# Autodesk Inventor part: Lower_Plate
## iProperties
Shininess: 15.0
Length Units: 11272
Angle Units: 11279
Time Units: 11290
Mass Units: 11283
Length Display Precision: 2
Angle Display Precision: 1
Created: 1999-05
Part Number: Lower_Plate
Document SubType Name: Modeling
Designer: Administrator
Density: 8.83 g/cm^3
Density: 8.83
Volumn: 8.899101648082546
Area: 68.18129680210748
PropertySet Name: Model Information
Control State: 0
Master: False
Checked Out: False
Author: Administrator
